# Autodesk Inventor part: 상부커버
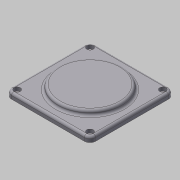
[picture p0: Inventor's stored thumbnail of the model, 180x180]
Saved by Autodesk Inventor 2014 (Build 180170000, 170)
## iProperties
Created: 2018-09
Part Number: 상부커버
Document SubType Name: Modeling
Density: 2.71 g/cm^3
Material: 알루미늄 6061
Mass: 285.163 g
Surface Area: 256.153 cm^2
Volume: 105.226 cm^3
Appearance: 알루미늄 - 평지
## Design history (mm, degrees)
sketch "스케치5"
  geometry: L1 (-52.5, -52.5)-(52.5, -52.5); L2 (52.5, -52.5)-(52.5, 52.5); L3 (52.5, 52.5)-(-52.5, 52.5); L4 (-52.5, 52.5)-(-52.5, -52.5); L5 (-52.5, -52.5)-(52.5, 52.5); L6 (52.5, -52.5)-(-52.5, 52.5); 1 further point
  constraints: 12 end point, 2 midpoint, 2 parallel, 1 horizontal, 1 perpendicular
  dimensions: "d35" = 105 distance of L3.end L2.end; "d36" = 105 distance of L2.end L1.end
extrude "돌출4" new body sketch "스케치5" distance "d37" = 7; taper "d38" = 0 deg
fillet "모깎기4" dims "d39" = 7
sketch "스케치2"
  geometry: C1 r 40 at (0, 0); 2 further points
  constraints: 2 coincident, 1 centre point
  dimensions: "d4" = 80 diameter of C1
extrude "돌출3" join sketch "스케치2" distance "d5" = 6; taper "d6" = 0 deg
fillet "모깎기1" dims "d7" = 3
sketch "스케치4"
  geometry: L1 (52.5, -45.5)-(52.5, 45.5) reference; L2 (-45.5, -52.5)-(45.5, -52.5) reference; L3 (-52.5, 45.5)-(-52.5, -45.5) reference; L4 (45.5, 52.5)-(-45.5, 52.5) reference; A1 r 7 centre (45.5, 45.5) between (52.5, 45.5) and (45.5, 52.5) reference; A2 r 7 centre (45.5, -45.5) between (45.5, -52.5) and (52.5, -45.5) reference; A3 r 7 centre (-45.5, -45.5) between (-52.5, -45.5) and (-45.5, -52.5) reference; A4 r 7 centre (-45.5, 45.5) between (-45.5, 52.5) and (-52.5, 45.5) reference; 4 further points
  constraints: 4 coincident
hole "구멍3" sketch "스케치4" at (-45.5, 45.5), (-45.5, -45.5), (45.5, -45.5), (45.5, 45.5) diameter "d43" = 4.5; stored, may be unused: countersink angle "d47" = 90 deg, drill point angle "d49" = 118 deg; dims "d44" = 6, "d45" = 8, "d46" = 4.4, "d48" = 8
fillet "모깎기3" dims "d19" = 3
node "솔리드1"
node "솔리드2"
node "투영된 루프2"
